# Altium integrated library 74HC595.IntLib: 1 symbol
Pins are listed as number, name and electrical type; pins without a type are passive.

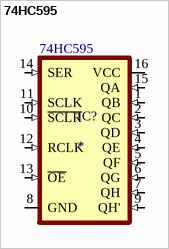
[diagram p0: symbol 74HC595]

## 74HC595
designator IC?
Shift Register Single 8-Bit Serial to Serial/Parallel 16-Pin SSOP T/R; MF: Nexperia; MP: 74HC595
footprint SO16
pins: 1 QB (in), 2 QC (in), 3 QD (in), 4 QE (in), 5 QF (in), 6 QG (in), 7 QH (in), 8 GND (power), 9 QH' (in), 10 ~{SCLR} (in), 11 SCLK (in), 12 RCLK (in), 13 ~{OE} (in), 14 SER (in), 15 QA (in), 16 VCC (power)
